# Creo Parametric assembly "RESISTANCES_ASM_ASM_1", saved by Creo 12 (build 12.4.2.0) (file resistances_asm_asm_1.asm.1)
Units: Custom; MM, KILOGRAM, SECS

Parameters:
  PTC_WM_ITERATION = "0"
  PTC_WM_VERSION = "-.0"
  PTC_WM_LIFECYCLE_STATE = "In Work"
  PTC_WM_LIFECYCLE = "MO_CADDocument"
  PTC_WM_CREATED_BY = "Maximilian Roepper (Z0017RMS: MO)"
  PTC_WM_CREATED_ON = "18-Sep-26 11:36:42 AM"
  PTC_WM_MODIFIED_BY = "Maximilian Roepper (Z0017RMS: MO)"
  PTC_WM_MODIFIED_ON = "18-Sep-26 11:36:46 AM"
  PDMLINKNUMBER = "PDM000071454966"
  PTC_WM_NUMBER = "PDM000071454966"

Other parameters: WEIGHT, WEIGHT_FACTOR, WEIGHT_ADD, MC_ERRORS, SUPPLIER

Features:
  1. coordinate system
  2. imported feature
  3. component "R_0603__PRT_1"
  4. component "R_0603_001_PRT_1"
  5. component "R_0603_002_PRT_1"
  6. component "R_0603_003_PRT_1"
  7. component "R_0603_004_PRT_1"
  8. component "R_0603_005_PRT_1"
  9. component "R_0603_006_PRT_1"
  10. component "R_0603_007_PRT_1"
  11. component "R_0402_001_PRT_1"
  12. component "R_0402_002_PRT_1"
  13. component "R_0603_008_PRT_1"

Other named items: DRW_VIEW_ORG, ROUGH-GROB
